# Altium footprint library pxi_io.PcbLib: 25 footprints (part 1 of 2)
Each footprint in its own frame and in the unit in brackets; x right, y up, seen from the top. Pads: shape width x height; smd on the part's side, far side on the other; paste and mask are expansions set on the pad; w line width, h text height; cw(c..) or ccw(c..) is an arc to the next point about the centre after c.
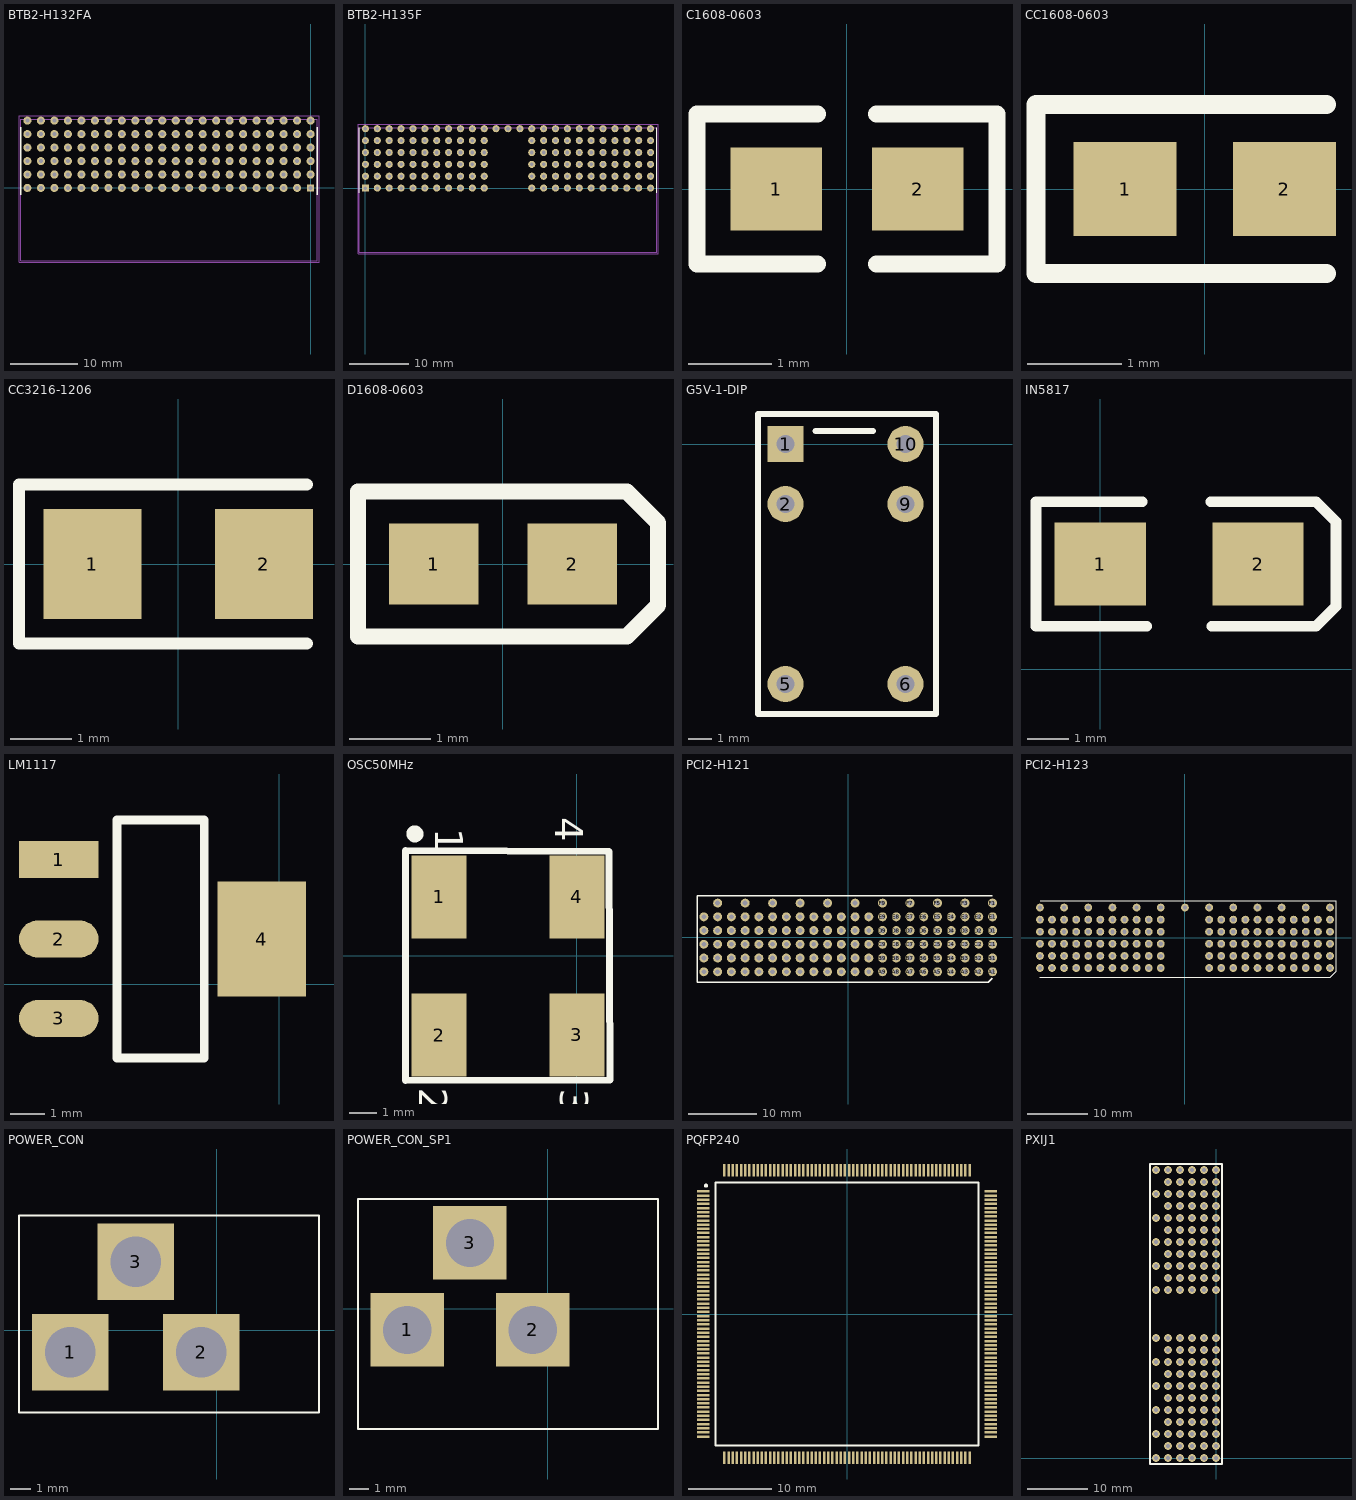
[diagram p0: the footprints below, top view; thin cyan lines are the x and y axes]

## BTB2-H132FA [mm] "Board-to-Board Connector, Right Angle, Pitch 2mm, 132-Position, Female"
height 7.7
pads (132):
  rect 1x1 / inner round 1.524 / far side round 1.524 hole 0.61: A1(0,0)
  round 1.2 hole 0.61: A2(-2,0) A3(-4,0) A4(-6,0) A5(-8,0) A6(-10,0) A7(-12,0) A8(-14,0) A9(-16,0) A10(-18,0) A11(-20,0) A12(-22,0) A13(-24,0) A14(-26,0) A15(-28,0) A16(-30,0) A17(-32,0) A18(-34,0) A19(-36,0) A20(-38,0) A21(-40,0) A22(-42,0) B1(0,2) B2(-2,2) B3(-4,2) B4(-6,2) B5(-8,2) B6(-10,2) B7(-12,2) B8(-14,2) B9(-16,2) B10(-18,2) B11(-20,2) B12(-22,2) B13(-24,2) B14(-26,2) B15(-28,2) B16(-30,2) B17(-32,2) B18(-34,2) B19(-36,2) B20(-38,2) B21(-40,2) B22(-42,2) C1(0,4) C2(-2,4) C3(-4,4) C4(-6,4) C5(-8,4) C6(-10,4) C7(-12,4) C8(-14,4) C9(-16,4) C10(-18,4) C11(-20,4) C12(-22,4) C13(-24,4) C14(-26,4) C15(-28,4) C16(-30,4) C17(-32,4) C18(-34,4) C19(-36,4) C20(-38,4) C21(-40,4) C22(-42,4) D1(0,6) D2(-2,6) D3(-4,6) D4(-6,6) D5(-8,6) D6(-10,6) D7(-12,6) D8(-14,6) D9(-16,6) D10(-18,6) D11(-20,6) D12(-22,6) D13(-24,6) D14(-26,6) D15(-28,6) D16(-30,6) D17(-32,6) D18(-34,6) D19(-36,6) D20(-38,6) D21(-40,6) D22(-42,6) E1(0,8) E2(-2,8) E3(-4,8) E4(-6,8) E5(-8,8) E6(-10,8) E7(-12,8) E8(-14,8) E9(-16,8) E10(-18,8) E11(-20,8) E12(-22,8) E13(-24,8) E14(-26,8) E15(-28,8) E16(-30,8) E17(-32,8) E18(-34,8) E19(-36,8) E20(-38,8) E21(-40,8) E22(-42,8) F1(0,10) F2(-2,10) F3(-4,10) F4(-6,10) F5(-8,10) F6(-10,10) F7(-12,10) F8(-14,10) F9(-16,10) F10(-18,10) F11(-20,10) F12(-22,10) F13(-24,10) F14(-26,10) F15(-28,10) F16(-30,10) F17(-32,10) F18(-34,10) F19(-36,10) F20(-38,10) F21(-40,10) F22(-42,10)
Top Overlay:
  lines w0.2: -43,-1 -43,9 ; 1,-1 1,9
Mechanical 13:
  lines w0.1: -43,-10.8 -43,10.2 1,10.2 1,-10.8 -43,-10.8
Mechanical 15:
  lines w0.1: -0.5,0 0.5,0 ; 0,-0.5 0,0.5 ; -43.25,-11.05 1.25,-11.05 1.25,10.75 -43.25,10.75 -43.25,-11.05
3D body: height 7.25, standoff 0, extent -43,-2 1,9.4
3D body: height 7.7, standoff -3.7, extent -43,-10.8 0.95,-2.032
3D body: height 7.39, standoff 0.7, extent -42.418,9.8 0.65,10.2
3D body: height 7.8, standoff 7.39, extent -42.418,0.972 0.65,10.2
3D body: height 7.8, standoff 7.39, extent -42.418,-6.38 0.65,0.972
3D body: height 0, standoff -3.3, extent -0.198,-0.199 0.2,0.2
3D body: height 0, standoff -3.3, extent -0.198,1.801 0.2,2.2
3D body: height 0, standoff -3.3, extent -0.198,3.801 0.2,4.2
3D body: height 0, standoff -3.3, extent -0.198,5.801 0.2,6.2
3D body: height 0, standoff -3.3, extent -0.198,7.801 0.2,8.2
3D body: height 0, standoff -3.3, extent -2.198,7.801 -1.8,8.2
3D body: height 0, standoff -3.3, extent -2.198,5.801 -1.8,6.2
3D body: height 0, standoff -3.3, extent -2.198,3.801 -1.8,4.2
3D body: height 0, standoff -3.3, extent -2.198,1.801 -1.8,2.2
3D body: height 0, standoff -3.3, extent -2.198,-0.199 -1.8,0.2
3D body: height 0, standoff -3.3, extent -4.198,7.801 -3.8,8.2
3D body: height 0, standoff -3.3, extent -4.198,5.801 -3.8,6.2
3D body: height 0, standoff -3.3, extent -4.198,3.801 -3.8,4.2
3D body: height 0, standoff -3.3, extent -4.198,1.801 -3.8,2.2
3D body: height 0, standoff -3.3, extent -4.198,-0.199 -3.8,0.2
3D body: height 0, standoff -3.3, extent -6.198,7.801 -5.8,8.2
3D body: height 0, standoff -3.3, extent -6.198,5.801 -5.8,6.2
3D body: height 0, standoff -3.3, extent -6.198,3.801 -5.8,4.2
3D body: height 0, standoff -3.3, extent -6.198,1.801 -5.8,2.2
3D body: height 0, standoff -3.3, extent -6.198,-0.199 -5.8,0.2
3D body: height 0, standoff -3.3, extent -8.198,7.801 -7.8,8.2
3D body: height 0, standoff -3.3, extent -8.198,5.801 -7.8,6.2
3D body: height 0, standoff -3.3, extent -8.198,3.801 -7.8,4.2
3D body: height 0, standoff -3.3, extent -8.198,1.801 -7.8,2.2
3D body: height 0, standoff -3.3, extent -8.198,-0.199 -7.8,0.2
3D body: height 0, standoff -3.3, extent -10.198,7.801 -9.8,8.2
3D body: height 0, standoff -3.3, extent -10.198,5.801 -9.8,6.2
3D body: height 0, standoff -3.3, extent -10.198,3.801 -9.8,4.2
3D body: height 0, standoff -3.3, extent -10.198,1.801 -9.8,2.2
3D body: height 0, standoff -3.3, extent -10.198,-0.199 -9.8,0.2
3D body: height 0, standoff -3.3, extent -12.198,7.801 -11.8,8.2
3D body: height 0, standoff -3.3, extent -12.198,5.801 -11.8,6.2
3D body: height 0, standoff -3.3, extent -12.198,3.801 -11.8,4.2
3D body: height 0, standoff -3.3, extent -12.198,1.801 -11.8,2.2
3D body: height 0, standoff -3.3, extent -12.198,-0.199 -11.8,0.2
3D body: height 0, standoff -3.3, extent -14.198,7.801 -13.8,8.2
3D body: height 0, standoff -3.3, extent -14.198,5.801 -13.8,6.2
3D body: height 0, standoff -3.3, extent -14.198,3.801 -13.8,4.2
3D body: height 0, standoff -3.3, extent -14.198,1.801 -13.8,2.2
3D body: height 0, standoff -3.3, extent -14.198,-0.199 -13.8,0.2
3D body: height 0, standoff -3.3, extent -16.198,7.801 -15.8,8.2
3D body: height 0, standoff -3.3, extent -16.198,5.801 -15.8,6.2
3D body: height 0, standoff -3.3, extent -16.198,3.801 -15.8,4.2
3D body: height 0, standoff -3.3, extent -16.198,1.801 -15.8,2.2
3D body: height 0, standoff -3.3, extent -16.198,-0.199 -15.8,0.2
3D body: height 0, standoff -3.3, extent -18.198,7.801 -17.8,8.2
3D body: height 0, standoff -3.3, extent -18.198,5.801 -17.8,6.2
3D body: height 0, standoff -3.3, extent -18.198,3.801 -17.8,4.2
3D body: height 0, standoff -3.3, extent -18.198,1.801 -17.8,2.2
3D body: height 0, standoff -3.3, extent -18.198,-0.199 -17.8,0.2
3D body: height 0, standoff -3.3, extent -20.198,7.801 -19.8,8.2
3D body: height 0, standoff -3.3, extent -20.198,5.801 -19.8,6.2
3D body: height 0, standoff -3.3, extent -20.198,3.801 -19.8,4.2
3D body: height 0, standoff -3.3, extent -20.198,1.801 -19.8,2.2
3D body: height 0, standoff -3.3, extent -20.198,-0.199 -19.8,0.2
3D body: height 0, standoff -3.3, extent -22.198,7.801 -21.8,8.2
3D body: height 0, standoff -3.3, extent -22.198,5.801 -21.8,6.2
3D body: height 0, standoff -3.3, extent -22.198,3.801 -21.8,4.2
3D body: height 0, standoff -3.3, extent -22.198,1.801 -21.8,2.2
3D body: height 0, standoff -3.3, extent -22.198,-0.199 -21.8,0.2
3D body: height 0, standoff -3.3, extent -24.198,7.801 -23.8,8.2
3D body: height 0, standoff -3.3, extent -24.198,5.801 -23.8,6.2
3D body: height 0, standoff -3.3, extent -24.198,3.801 -23.8,4.2
3D body: height 0, standoff -3.3, extent -24.198,1.801 -23.8,2.2
3D body: height 0, standoff -3.3, extent -24.198,-0.199 -23.8,0.2
3D body: height 0, standoff -3.3, extent -26.198,7.801 -25.8,8.2
3D body: height 0, standoff -3.3, extent -26.198,5.801 -25.8,6.2
3D body: height 0, standoff -3.3, extent -26.198,3.801 -25.8,4.2
3D body: height 0, standoff -3.3, extent -26.198,1.801 -25.8,2.2
3D body: height 0, standoff -3.3, extent -26.198,-0.199 -25.8,0.2
3D body: height 0, standoff -3.3, extent -28.198,7.801 -27.8,8.2
3D body: height 0, standoff -3.3, extent -28.198,5.801 -27.8,6.2
3D body: height 0, standoff -3.3, extent -28.198,3.801 -27.8,4.2
3D body: height 0, standoff -3.3, extent -28.198,1.801 -27.8,2.2
3D body: height 0, standoff -3.3, extent -28.198,-0.199 -27.8,0.2
3D body: height 0, standoff -3.3, extent -30.198,7.801 -29.8,8.2
3D body: height 0, standoff -3.3, extent -30.198,5.801 -29.8,6.2
3D body: height 0, standoff -3.3, extent -30.198,3.801 -29.8,4.2
3D body: height 0, standoff -3.3, extent -30.198,1.801 -29.8,2.2
3D body: height 0, standoff -3.3, extent -30.198,-0.199 -29.8,0.2
3D body: height 0, standoff -3.3, extent -32.198,7.801 -31.8,8.2
3D body: height 0, standoff -3.3, extent -32.198,5.801 -31.8,6.2
3D body: height 0, standoff -3.3, extent -32.198,3.801 -31.8,4.2
3D body: height 0, standoff -3.3, extent -32.198,1.801 -31.8,2.2
3D body: height 0, standoff -3.3, extent -32.198,-0.199 -31.8,0.2
3D body: height 0, standoff -3.3, extent -34.198,7.801 -33.8,8.2
3D body: height 0, standoff -3.3, extent -34.198,5.801 -33.8,6.2
3D body: height 0, standoff -3.3, extent -34.198,3.801 -33.8,4.2
3D body: height 0, standoff -3.3, extent -34.198,1.801 -33.8,2.2
3D body: height 0, standoff -3.3, extent -34.198,-0.199 -33.8,0.2
3D body: height 0, standoff -3.3, extent -36.198,7.801 -35.8,8.2
3D body: height 0, standoff -3.3, extent -36.198,5.801 -35.8,6.2
3D body: height 0, standoff -3.3, extent -36.198,3.801 -35.8,4.2
3D body: height 0, standoff -3.3, extent -36.198,1.801 -35.8,2.2
3D body: height 0, standoff -3.3, extent -36.198,-0.199 -35.8,0.2
3D body: height 0, standoff -3.3, extent -38.198,-0.199 -37.8,0.2
3D body: height 0, standoff -3.3, extent -38.198,1.801 -37.8,2.2
3D body: height 0, standoff -3.3, extent -38.198,3.801 -37.8,4.2
3D body: height 0, standoff -3.3, extent -38.198,5.801 -37.8,6.2
3D body: height 0, standoff -3.3, extent -38.198,7.801 -37.8,8.2
3D body: height 0, standoff -3.3, extent -40.198,-0.199 -39.8,0.2
3D body: height 0, standoff -3.3, extent -40.198,1.801 -39.8,2.2
3D body: height 0, standoff -3.3, extent -40.198,3.801 -39.8,4.2
3D body: height 0, standoff -3.3, extent -40.198,5.801 -39.8,6.2
3D body: height 0, standoff -3.3, extent -40.198,7.801 -39.8,8.2
3D body: height 0, standoff -3.3, extent -42.198,-0.2 -41.8,0.2
3D body: height 0, standoff -3.3, extent -42.198,1.8 -41.8,2.2
3D body: height 0, standoff -3.3, extent -42.198,3.8 -41.8,4.2
3D body: height 0, standoff -3.3, extent -42.198,5.8 -41.8,6.2
3D body: height 0, standoff -3.3, extent -42.198,7.8 -41.8,8.2
3D body: height 0.7, standoff -3.3, extent -40.198,9.8 -39.8,10.2
3D body: height 0.7, standoff -3.3, extent -0.198,9.8 0.2,10.2
3D body: height 0.7, standoff -3.3, extent -4.198,9.8 -3.8,10.2
3D body: height 0.7, standoff -3.3, extent -8.198,9.8 -7.8,10.2
3D body: height 0.7, standoff -3.3, extent -12.198,9.8 -11.8,10.2
3D body: height 0.7, standoff -3.3, extent -16.198,9.8 -15.8,10.2
3D body: height 0.7, standoff -3.3, extent -20.198,9.8 -19.8,10.2
3D body: height 0.7, standoff -3.3, extent -24.198,9.8 -23.8,10.2
3D body: height 0.7, standoff -3.3, extent -28.198,9.8 -27.8,10.2
3D body: height 0.7, standoff -3.3, extent -32.198,9.8 -31.8,10.2
3D body: height 0.7, standoff -3.3, extent -36.198,9.8 -35.8,10.2

## BTB2-H135F [mm] "Board-to-Board Connector, Right Angle, Pitch 2mm, 135-Position, Female"
pads (135):
  rect 1.2x1.2 hole 0.61: A1(0,0)
  round 1.2 hole 0.61: A2(2,0) A3(4,0) A4(6,0) A5(8,0) A6(10,0) A7(12,0) A8(14,0) A9(16,0) A10(18,0) A11(20,0) A15(28,0) A16(30,0) A17(32,0) A18(34,0) A19(36,0) A20(38,0) A21(40,0) A22(42,0) A23(44,0) A24(46,0) A25(48,0) B1(0,2) B2(2,2) B3(4,2) B4(6,2) B5(8,2) B6(10,2) B7(12,2) B8(14,2) B9(16,2) B10(18,2) B11(20,2) B15(28,2) B16(30,2) B17(32,2) B18(34,2) B19(36,2) B20(38,2) B21(40,2) B22(42,2) B23(44,2) B24(46,2) B25(48,2) C1(0,4) C2(2,4) C3(4,4) C4(6,4) C5(8,4) C6(10,4) C7(12,4) C8(14,4) C9(16,4) C10(18,4) C11(20,4) C15(28,4) C16(30,4) C17(32,4) C18(34,4) C19(36,4) C20(38,4) C21(40,4) C22(42,4) C23(44,4) C24(46,4) C25(48,4) D1(0,6) D2(2,6) D3(4,6) D4(6,6) D5(8,6) D6(10,6) D7(12,6) D8(14,6) D9(16,6) D10(18,6) D11(20,6) D15(28,6) D16(30,6) D17(32,6) D18(34,6) D19(36,6) D20(38,6) D21(40,6) D22(42,6) D23(44,6) D24(46,6) D25(48,6) E1(0,8) E2(2,8) E3(4,8) E4(6,8) E5(8,8) E6(10,8) E7(12,8) E8(14,8) E9(16,8) E10(18,8) E11(20,8) E15(28,8) E16(30,8) E17(32,8) E18(34,8) E19(36,8) E20(38,8) E21(40,8) E22(42,8) E23(44,8) E24(46,8) E25(48,8) F1(0,10) F2(2,10) F3(4,10) F4(6,10) F5(8,10) F6(10,10) F7(12,10) F8(14,10) F9(16,10) F10(18,10) F11(20,10) F12(22,10) F13(24,10) F14(26,10) F15(28,10) F16(30,10) F17(32,10) F18(34,10) F19(36,10) F20(38,10) F21(40,10) F22(42,10) F23(44,10) F24(46,10) F25(48,10)
Top Overlay:
  lines w0.2: -1,-0.8 -1,10.2 ; 49,-0.8 49,10.2
Mechanical 13:
  lines w0.1: -1,-10.8 49,-10.8 49,10.2 -1,10.2 -1,-10.8
Mechanical 15:
  lines w0.1: -0.5,0 0.5,0 ; 0,-0.5 0,0.5 ; -1.25,-11.05 49.25,-11.05 49.25,10.75 -1.25,10.75 -1.25,-11.05
3D body: height 8.08, standoff 6.75, extent 22.175,-13.8 25.825,-8.725
3D body: height -2.85, standoff -4.18, extent 22.5,-13.8 25.5,-8.725
3D body: height 7.65, standoff 6.75, extent 22.175,-8.725 25.825,-2.65
3D body: height -2.85, standoff -3.75, extent 22.175,-8.725 25.825,-2.65
3D body: height 7.65, standoff 0.5, extent 27,-10.8 48.95,-0.9
3D body: height 7.65, standoff 0.5, extent -0.95,-10.8 21,-0.9
3D body: height 2.87, standoff 0, extent 27,8.9 48.95,9.4
3D body: height 2.87, standoff 0, extent -0.95,8.9 21,9.4
3D body: height 7.25, standoff 0.5, extent 27,-0.9 48.95,8.9
3D body: height 7.25, standoff 0.5, extent -0.95,-0.9 21,8.9
3D body: height 0.5, standoff 0, extent 27,-2 48.95,-0.9
3D body: height 0.5, standoff 0, extent -0.95,-2 21,-0.9
3D body: height 3.26, standoff -0.94, extent -0.95,-10.8 21,-2
3D body: height 3.26, standoff -0.94, extent 27,-10.8 48.95,-2
3D body: height 2.91, standoff -1.29, extent -0.268,9.731 0.27,10.27
3D body: height 2.91, standoff -1.29, extent 3.732,9.731 4.27,10.27
3D body: height 2.91, standoff -1.29, extent 7.732,9.731 8.27,10.27
3D body: height 2.91, standoff -1.29, extent 11.732,9.731 12.27,10.27
3D body: height 2.91, standoff -1.29, extent 15.732,9.731 16.27,10.27
3D body: height 2.91, standoff -1.29, extent 19.732,9.731 20.27,10.27
3D body: height 2.91, standoff -1.29, extent 23.732,9.731 24.27,10.27
3D body: height 2.91, standoff -1.29, extent 27.732,9.731 28.27,10.27
3D body: height 2.91, standoff -1.29, extent 31.732,9.731 32.27,10.27
3D body: height 2.91, standoff -1.29, extent 35.732,9.731 36.27,10.27
3D body: height 2.91, standoff -1.29, extent 39.732,9.731 40.27,10.27
3D body: height 2.91, standoff -1.29, extent 43.732,9.731 44.27,10.27
3D body: height 2.91, standoff -1.29, extent 47.732,9.731 48.27,10.27
3D body: height 2.86, standoff -0.94, extent 47.702,7.701 48.3,8.299
3D body: height 2.86, standoff -0.94, extent -0.298,7.701 0.3,8.3
3D body: height 2.86, standoff -0.94, extent 1.702,7.701 2.3,8.3
3D body: height 2.86, standoff -0.94, extent 3.702,7.701 4.3,8.3
3D body: height 2.86, standoff -0.94, extent 5.702,7.701 6.3,8.3
3D body: height 2.86, standoff -0.94, extent 7.702,7.701 8.3,8.3
3D body: height 2.86, standoff -0.94, extent 9.702,7.701 10.3,8.3
3D body: height 2.86, standoff -0.94, extent 11.702,7.701 12.3,8.3
3D body: height 2.86, standoff -0.94, extent 13.702,7.701 14.3,8.3
3D body: height 2.86, standoff -0.94, extent 15.702,7.701 16.3,8.3
3D body: height 2.86, standoff -0.94, extent 17.702,7.701 18.3,8.3
3D body: height 2.86, standoff -0.94, extent 19.702,7.701 20.3,8.3
3D body: height 2.86, standoff -0.94, extent -0.298,5.701 0.3,6.3
3D body: height 2.86, standoff -0.94, extent 1.702,5.701 2.3,6.3
3D body: height 2.86, standoff -0.94, extent 3.702,5.701 4.3,6.3
3D body: height 2.86, standoff -0.94, extent 5.702,5.701 6.3,6.3
3D body: height 2.86, standoff -0.94, extent 7.702,5.701 8.3,6.3
3D body: height 2.86, standoff -0.94, extent 9.702,5.701 10.3,6.3
3D body: height 2.86, standoff -0.94, extent 11.702,5.701 12.3,6.3
3D body: height 2.86, standoff -0.94, extent 13.702,5.701 14.3,6.3
3D body: height 2.86, standoff -0.94, extent 15.702,5.701 16.3,6.3
3D body: height 2.86, standoff -0.94, extent 17.702,5.701 18.3,6.3
3D body: height 2.86, standoff -0.94, extent 19.702,5.701 20.3,6.3
3D body: height 2.86, standoff -0.94, extent 19.702,3.701 20.3,4.299
3D body: height 2.86, standoff -0.94, extent 17.702,3.701 18.3,4.299
3D body: height 2.86, standoff -0.94, extent 15.702,3.701 16.3,4.299
3D body: height 2.86, standoff -0.94, extent 13.702,3.701 14.3,4.299
3D body: height 2.86, standoff -0.94, extent 11.702,3.701 12.3,4.299
3D body: height 2.86, standoff -0.94, extent 9.702,3.701 10.3,4.299
3D body: height 2.86, standoff -0.94, extent 7.702,3.701 8.3,4.299
3D body: height 2.86, standoff -0.94, extent 5.702,3.701 6.3,4.299
3D body: height 2.86, standoff -0.94, extent 3.702,3.701 4.3,4.299
3D body: height 2.86, standoff -0.94, extent 1.702,3.701 2.3,4.299
3D body: height 2.86, standoff -0.94, extent -0.298,3.701 0.3,4.299
3D body: height 2.86, standoff -0.94, extent 19.702,1.701 20.3,2.299
3D body: height 2.86, standoff -0.94, extent 17.702,1.701 18.3,2.299
3D body: height 2.86, standoff -0.94, extent 15.702,1.701 16.3,2.299
3D body: height 2.86, standoff -0.94, extent 13.702,1.701 14.3,2.299
3D body: height 2.86, standoff -0.94, extent 11.702,1.701 12.3,2.299
3D body: height 2.86, standoff -0.94, extent 9.702,1.701 10.3,2.299
3D body: height 2.86, standoff -0.94, extent 7.702,1.701 8.3,2.299
3D body: height 2.86, standoff -0.94, extent 5.702,1.701 6.3,2.299
3D body: height 2.86, standoff -0.94, extent 3.702,1.701 4.3,2.299
3D body: height 2.86, standoff -0.94, extent 1.702,1.701 2.3,2.299
3D body: height 2.86, standoff -0.94, extent -0.298,1.701 0.3,2.299
3D body: height 2.86, standoff -0.94, extent 19.702,-0.299 20.3,0.299
3D body: height 2.86, standoff -0.94, extent 17.702,-0.299 18.3,0.299
3D body: height 2.86, standoff -0.94, extent 15.702,-0.299 16.3,0.299
3D body: height 2.86, standoff -0.94, extent 13.702,-0.299 14.3,0.299
3D body: height 2.86, standoff -0.94, extent 11.702,-0.299 12.3,0.299
3D body: height 2.86, standoff -0.94, extent 9.702,-0.299 10.3,0.299
3D body: height 2.86, standoff -0.94, extent 7.702,-0.299 8.3,0.299
3D body: height 2.86, standoff -0.94, extent 5.702,-0.299 6.3,0.299
3D body: height 2.86, standoff -0.94, extent 3.702,-0.299 4.3,0.299
3D body: height 2.86, standoff -0.94, extent 1.702,-0.299 2.3,0.299
3D body: height 2.86, standoff -0.94, extent -0.298,-0.299 0.3,0.299
3D body: height 2.86, standoff -0.94, extent 47.702,-0.299 48.3,0.3
3D body: height 2.86, standoff -0.94, extent 45.702,-0.299 46.3,0.3
3D body: height 2.86, standoff -0.94, extent 43.702,-0.299 44.3,0.3
3D body: height 2.86, standoff -0.94, extent 41.702,-0.299 42.3,0.3
3D body: height 2.86, standoff -0.94, extent 39.702,-0.299 40.3,0.3
3D body: height 2.86, standoff -0.94, extent 37.702,-0.299 38.3,0.3
3D body: height 2.86, standoff -0.94, extent 35.702,-0.299 36.3,0.3
3D body: height 2.86, standoff -0.94, extent 33.702,-0.299 34.3,0.3
3D body: height 2.86, standoff -0.94, extent 31.702,-0.299 32.3,0.3
3D body: height 2.86, standoff -0.94, extent 29.702,-0.299 30.3,0.3
3D body: height 2.86, standoff -0.94, extent 27.702,-0.299 28.3,0.3
3D body: height 2.86, standoff -0.94, extent 47.702,1.701 48.3,2.299
3D body: height 2.86, standoff -0.94, extent 45.702,1.701 46.3,2.299
3D body: height 2.86, standoff -0.94, extent 43.702,1.701 44.3,2.299
3D body: height 2.86, standoff -0.94, extent 41.702,1.701 42.3,2.299
3D body: height 2.86, standoff -0.94, extent 39.702,1.701 40.3,2.299
3D body: height 2.86, standoff -0.94, extent 37.702,1.701 38.3,2.299
3D body: height 2.86, standoff -0.94, extent 35.702,1.701 36.3,2.299
3D body: height 2.86, standoff -0.94, extent 33.702,1.701 34.3,2.299
3D body: height 2.86, standoff -0.94, extent 31.702,1.701 32.3,2.299
3D body: height 2.86, standoff -0.94, extent 29.702,1.701 30.3,2.299
3D body: height 2.86, standoff -0.94, extent 27.702,1.701 28.3,2.299
3D body: height 2.86, standoff -0.94, extent 47.702,3.701 48.3,4.299
3D body: height 2.86, standoff -0.94, extent 45.702,3.701 46.3,4.299
3D body: height 2.86, standoff -0.94, extent 43.702,3.701 44.3,4.299
3D body: height 2.86, standoff -0.94, extent 41.702,3.701 42.3,4.299
3D body: height 2.86, standoff -0.94, extent 39.702,3.701 40.3,4.299
3D body: height 2.86, standoff -0.94, extent 37.702,3.701 38.3,4.299
3D body: height 2.86, standoff -0.94, extent 35.702,3.701 36.3,4.299
3D body: height 2.86, standoff -0.94, extent 33.702,3.701 34.3,4.299
3D body: height 2.86, standoff -0.94, extent 31.702,3.701 32.3,4.299
3D body: height 2.86, standoff -0.94, extent 29.702,3.701 30.3,4.299
3D body: height 2.86, standoff -0.94, extent 27.702,3.701 28.3,4.299
3D body: height 2.86, standoff -0.94, extent 47.702,5.701 48.3,6.299
3D body: height 2.86, standoff -0.94, extent 45.702,5.701 46.3,6.299
3D body: height 2.86, standoff -0.94, extent 43.702,5.701 44.3,6.299
3D body: height 2.86, standoff -0.94, extent 41.702,5.701 42.3,6.299
3D body: height 2.86, standoff -0.94, extent 39.702,5.701 40.3,6.299
3D body: height 2.86, standoff -0.94, extent 37.702,5.701 38.3,6.299
3D body: height 2.86, standoff -0.94, extent 35.702,5.701 36.3,6.299
3D body: height 2.86, standoff -0.94, extent 33.702,5.701 34.3,6.299
3D body: height 2.86, standoff -0.94, extent 31.702,5.701 32.3,6.299
3D body: height 2.86, standoff -0.94, extent 29.702,5.701 30.3,6.299
3D body: height 2.86, standoff -0.94, extent 27.702,5.701 28.3,6.299
3D body: height 2.86, standoff -0.94, extent 45.702,7.701 46.3,8.299
3D body: height 2.86, standoff -0.94, extent 43.702,7.701 44.3,8.299
3D body: height 2.86, standoff -0.94, extent 41.702,7.701 42.3,8.299
3D body: height 2.86, standoff -0.94, extent 39.702,7.701 40.3,8.299
3D body: height 2.86, standoff -0.94, extent 37.702,7.701 38.3,8.299
3D body: height 2.86, standoff -0.94, extent 35.702,7.701 36.3,8.299
3D body: height 2.86, standoff -0.94, extent 33.702,7.701 34.3,8.299
3D body: height 2.86, standoff -0.94, extent 31.702,7.701 32.3,8.299
3D body: height 2.86, standoff -0.94, extent 29.702,7.701 30.3,8.299
3D body: height 2.86, standoff -0.94, extent 27.702,7.701 28.3,8.299
3D body: height 7.65, standoff 0.85, extent -0.85,9.8 48.85,10.2
3D body: height 7.65, standoff 7.25, extent -0.85,-2 48.85,10.2
3D body: height 7.65, standoff -2.96, extent 21,-2.65 27,-2

## C1608-0603 [mm]
pads (2):
  rect 1.1x1 smd: 1(-0.85,0) 2(0.85,0)
Top Overlay:
  lines w0.2: -0.35,-0.9 -1.8,-0.9 -1.8,0.9 -0.35,0.9 ; 0.35,-0.9 1.8,-0.9 1.8,0.9 0.35,0.9

## CC1608-0603 [mm]
pads (2):
  rect 1.1x1 smd: 1(-0.85,0) 2(0.85,0)
Top Overlay:
  lines w0.2: 1.3,-0.9 -1.8,-0.9 -1.8,0.9 1.3,0.9

## CC3216-1206 [mm]
pads (2):
  rect 1.6x1.8 smd: 1(-1.4,0) 2(1.4,0)
Top Overlay:
  lines w0.2: 2.1,-1.3 -2.6,-1.3 -2.6,1.3 2.1,1.3

## D1608-0603 [mm]
pads (2):
  rect 1.1x1 smd: 1(-0.85,0) 2(0.85,0)
Top Overlay:
  lines w0.2: 1.27,-0.889 1.524,-0.889 1.905,-0.508 1.905,0.508 1.524,0.889 1.27,0.889 ; 1.3,-0.889 -1.778,-0.889 -1.778,0.889 1.3,0.889

## G5V-1-DIP [mil]
pads (6):
  rect 60x60 hole 30: 1(200,0)
  round 60 hole 30: 2(200,-100) 5(200,-400) 6(400,-400) 9(400,-100) 10(400,0)
Top Overlay:
  lines w10: 250,22 346,22 ; 154,-450 154,50 451,50 451,-450 154,-450

## IN5817 [mm]
pads (2):
  rect 2.2x2 smd: 1(0,2.54) 2(3.81,2.54)
Top Overlay:
  lines w0.254: 1.016,4.039 -1.549,4.039 -1.549,1.041 1.118,1.041 ; 2.667,4.039 5.207,4.039 5.69,3.556 5.69,1.524 5.207,1.041 2.692,1.041

## LM1117 [mil]
pads (4):
  rect 90x42 smd: 1(-250,141)
  oval 90x42 smd: 2(-250,51) 3(-250,-39)
  rect 100x130 smd: 4(-20,51)
Top Overlay:
  lines w10: -99,186 -184,186 -184,-84 -85,-84 -85,186 -97.5,186

## OSC50MHz [mm] "for 50MHz"
height 3.5
pads (4):
  rect 2x3 smd: 1(-5,2.134) 2(-5,-2.87) 3(0,-2.866) 4(0,2.134)
Top Overlay:
  circle w0.5: c-5.873,4.42 r0.057
  lines w0.254: -6.223,-4.521 -6.223,3.81 1.168,3.785 1.194,-4.496 -6.223,-4.521
  text "4" at -0.787,5.029 h1.02
  text "3" at -0.61,-4.826 h1.02
  text "2" at -5.715,-4.775 h1.02
  text "1" at -5.131,4.623 h1.02

## PCI2-H121 [mm]
pads (121):
  round 1.3 hole 0.7: A1(21,-5) A2(19,-5) A3(17,-5) A4(15,-5) A5(13,-5) A6(11,-5) A7(9,-5) A8(7,-5) A9(5,-5) A10(3,-5) A11(1,-5) A12(-1,-5) A13(-3,-5) A14(-5,-5) A15(-7,-5) A16(-9,-5) A17(-11,-5) A18(-13,-5) A19(-15,-5) A20(-17,-5) A21(-19,-5) A22(-21,-5) B1(21,-3) B2(19,-3) B3(17,-3) B4(15,-3) B5(13,-3) B6(11,-3) B7(9,-3) B8(7,-3) B9(5,-3) B10(3,-3) B11(1,-3) B12(-1,-3) B13(-3,-3) B14(-5,-3) B15(-7,-3) B16(-9,-3) B17(-11,-3) B18(-13,-3) B19(-15,-3) B20(-17,-3) B21(-19,-3) B22(-21,-3) C1(21,-1) C2(19,-1) C3(17,-1) C4(15,-1) C5(13,-1) C6(11,-1) C7(9,-1) C8(7,-1) C9(5,-1) C10(3,-1) C11(1,-1) C12(-1,-1) C13(-3,-1) C14(-5,-1) C15(-7,-1) C16(-9,-1) C17(-11,-1) C18(-13,-1) C19(-15,-1) C20(-17,-1) C21(-19,-1) C22(-21,-1) D1(21,1) D2(19,1) D3(17,1) D4(15,1) D5(13,1) D6(11,1) D7(9,1) D8(7,1) D9(5,1) D10(3,1) D11(1,1) D12(-1,1) D13(-3,1) D14(-5,1) D15(-7,1) D16(-9,1) D17(-11,1) D18(-13,1) D19(-15,1) D20(-17,1) D21(-19,1) D22(-21,1) E1(21,3) E2(19,3) E3(17,3) E4(15,3) E5(13,3) E6(11,3) E7(9,3) E8(7,3) E9(5,3) E10(3,3) E11(1,3) E12(-1,3) E13(-3,3) E14(-5,3) E15(-7,3) E16(-9,3) E17(-11,3) E18(-13,3) E19(-15,3) E20(-17,3) E21(-19,3) E22(-21,3) F1(21,5) F3(17,5) F5(13,5) F7(9,5) F9(5,5) F11(1,5) F13(-3,5) F15(-7,5) F17(-11,5) F19(-15,5) F21(-19,5)
Top Overlay:
  lines w0.2: 20.371,-6.502 -22,-6.5 -22,6.05 20.93,6.045
  lines w0.203: 20.371,-6.502 20.93,-5.944

## PCI2-H123 [mm]
pads (123):
  round 1.3 hole 0.7: A1(24,-5) A2(22,-5) A3(20,-5) A4(18,-5) A5(16,-5) A6(14,-5) A7(12,-5) A8(10,-5) A9(8,-5) A10(6,-5) A11(4,-5) A15(-4,-5) A16(-6,-5) A17(-8,-5) A18(-10,-5) A19(-12,-5) A20(-14,-5) A21(-16,-5) A22(-18,-5) A23(-20,-5) A24(-22,-5) A25(-24,-5) B1(24,-3) B2(22,-3) B3(20,-3) B4(18,-3) B5(16,-3) B6(14,-3) B7(12,-3) B8(10,-3) B9(8,-3) B10(6,-3) B11(4,-3) B15(-4,-3) B16(-6,-3) B17(-8,-3) B18(-10,-3) B19(-12,-3) B20(-14,-3) B21(-16,-3) B22(-18,-3) B23(-20,-3) B24(-22,-3) B25(-24,-3) C1(24,-1) C2(22,-1) C3(20,-1) C4(18,-1) C5(16,-1) C6(14,-1) C7(12,-1) C8(10,-1) C9(8,-1) C10(6,-1) C11(4,-1) C15(-4,-1) C16(-6,-1) C17(-8,-1) C18(-10,-1) C19(-12,-1) C20(-14,-1) C21(-16,-1) C22(-18,-1) C23(-20,-1) C24(-22,-1) C25(-24,-1) D1(24,1) D2(22,1) D3(20,1) D4(18,1) D5(16,1) D6(14,1) D7(12,1) D8(10,1) D9(8,1) D10(6,1) D11(4,1) D15(-4,1) D16(-6,1) D17(-8,1) D18(-10,1) D19(-12,1) D20(-14,1) D21(-16,1) D22(-18,1) D23(-20,1) D24(-22,1) D25(-24,1) E1(24,3) E2(22,3) E3(20,3) E4(18,3) E5(16,3) E6(14,3) E7(12,3) E8(10,3) E9(8,3) E10(6,3) E11(4,3) E15(-4,3) E16(-6,3) E17(-8,3) E18(-10,3) E19(-12,3) E20(-14,3) E21(-16,3) E22(-18,3) E23(-20,3) E24(-22,3) E25(-24,3) F1(24,5) F3(20,5) F5(16,5) F7(12,5) F9(8,5) F11(4,5) F13(0,5) F15(-4,5) F17(-8,5) F19(-12,5) F21(-16,5) F23(-20,5) F25(-24,5)
Top Overlay:
  lines w0.2: -24.028,-6.502 24.028,-6.5 25,-5.528 25,6.1 -23.978,6.096
  lines w0.203: 24.028,-6.5 25,-5.528 25,-5.283

## POWER_CON [mm]
pads (3):
  rect 3.8x3.8 hole 2.5: 1(-7.264,-1.092) 2(-0.764,-1.092) 3(-4.014,3.408)
Top Overlay:
  lines w0.102: -9.804,-4.064 5.08,-4.064 5.08,5.69 -9.804,5.69 -9.804,-4.064

## POWER_CON_SP1 [mm]
pads (3):
  rect 3.8x3.8 hole 2.5: 1(-7.264,-1.092) 2(-0.764,-1.092) 3(-4.014,3.408)
Top Overlay:
  lines w0.102: -9.804,-6.223 5.715,-6.223 5.715,5.69 -9.804,5.69 -9.804,-6.223

## PQFP240 [mm] "byTX chaned for cyclone FPGA"
pads (240):
  rect 1.5x0.3 smd: 1(-17.3,14.75) 2(-17.3,14.25) 3(-17.3,13.75) 4(-17.3,13.25) 5(-17.3,12.75) 6(-17.3,12.25) 7(-17.3,11.75) 8(-17.3,11.25) 9(-17.3,10.75) 10(-17.3,10.25) 11(-17.3,9.75) 12(-17.3,9.25) 13(-17.3,8.75) 14(-17.3,8.25) 15(-17.3,7.75) 16(-17.3,7.25) 17(-17.3,6.75) 18(-17.3,6.25) 19(-17.3,5.75) 20(-17.3,5.25) 21(-17.3,4.75) 22(-17.3,4.25) 23(-17.3,3.75) 24(-17.3,3.25) 25(-17.3,2.75) 26(-17.3,2.25) 27(-17.3,1.75) 28(-17.3,1.25) 29(-17.3,0.75) 30(-17.3,0.25) 31(-17.3,-0.25) 32(-17.3,-0.75) 33(-17.3,-1.25) 34(-17.3,-1.75) 35(-17.3,-2.25) 36(-17.3,-2.75) 37(-17.3,-3.25) 38(-17.3,-3.75) 39(-17.3,-4.25) 40(-17.3,-4.75) 41(-17.3,-5.25) 42(-17.3,-5.75) 43(-17.3,-6.25) 44(-17.3,-6.75) 45(-17.3,-7.25) 46(-17.3,-7.75) 47(-17.3,-8.25) 48(-17.3,-8.75) 49(-17.3,-9.25) 50(-17.3,-9.75) 51(-17.3,-10.25) 52(-17.3,-10.75) 53(-17.3,-11.25) 54(-17.3,-11.75) 55(-17.3,-12.25) 56(-17.3,-12.75) 57(-17.3,-13.25) 58(-17.3,-13.75) 59(-17.3,-14.25) 60(-17.3,-14.75) 121(17.3,-14.75) 122(17.3,-14.25) 123(17.3,-13.75) 124(17.3,-13.25) 125(17.3,-12.75) 126(17.3,-12.25) 127(17.3,-11.75) 128(17.3,-11.25) 129(17.3,-10.75) 130(17.3,-10.25) 131(17.3,-9.75) 132(17.3,-9.25) 133(17.3,-8.75) 134(17.3,-8.25) 135(17.3,-7.75) 136(17.3,-7.25) 137(17.3,-6.75) 138(17.3,-6.25) 139(17.3,-5.75) 140(17.3,-5.25) 141(17.3,-4.75) 142(17.3,-4.25) 143(17.3,-3.75) 144(17.3,-3.25) 145(17.3,-2.75) 146(17.3,-2.25) 147(17.3,-1.75) 148(17.3,-1.25) 149(17.3,-0.75) 150(17.3,-0.25) 151(17.3,0.25) 152(17.3,0.75) 153(17.3,1.25) 154(17.3,1.75) 155(17.3,2.25) 156(17.3,2.75) 157(17.3,3.25) 158(17.3,3.75) 159(17.3,4.25) 160(17.3,4.75) 161(17.3,5.25) 162(17.3,5.75) 163(17.3,6.25) 164(17.3,6.75) 165(17.3,7.25) 166(17.3,7.75) 167(17.3,8.25) 168(17.3,8.75) 169(17.3,9.25) 170(17.3,9.75) 171(17.3,10.25) 172(17.3,10.75) 173(17.3,11.25) 174(17.3,11.75) 175(17.3,12.25) 176(17.3,12.75) 177(17.3,13.25) 178(17.3,13.75) 179(17.3,14.25) 180(17.3,14.75)
  rect 0.3x1.5 smd: 61(-14.75,-17.3) 62(-14.25,-17.3) 63(-13.75,-17.3) 64(-13.25,-17.3) 65(-12.75,-17.3) 66(-12.25,-17.3) 67(-11.75,-17.3) 68(-11.25,-17.3) 69(-10.75,-17.3) 70(-10.25,-17.3) 71(-9.75,-17.3) 72(-9.25,-17.3) 73(-8.75,-17.3) 74(-8.25,-17.3) 75(-7.75,-17.3) 76(-7.25,-17.3) 77(-6.75,-17.3) 78(-6.25,-17.3) 79(-5.75,-17.3) 80(-5.25,-17.3) 81(-4.75,-17.3) 82(-4.25,-17.3) 83(-3.75,-17.3) 84(-3.25,-17.3) 85(-2.75,-17.3) 86(-2.25,-17.3) 87(-1.75,-17.3) 88(-1.25,-17.3) 89(-0.75,-17.3) 90(-0.25,-17.3) 91(0.25,-17.3) 92(0.75,-17.3) 93(1.25,-17.3) 94(1.75,-17.3) 95(2.25,-17.3) 96(2.75,-17.3) 97(3.25,-17.3) 98(3.75,-17.3) 99(4.25,-17.3) 100(4.75,-17.3) 101(5.25,-17.3) 102(5.75,-17.3) 103(6.25,-17.3) 104(6.75,-17.3) 105(7.25,-17.3) 106(7.75,-17.3) 107(8.25,-17.3) 108(8.75,-17.3) 109(9.25,-17.3) 110(9.75,-17.3) 111(10.25,-17.3) 112(10.75,-17.3) 113(11.25,-17.3) 114(11.75,-17.3) 115(12.25,-17.3) 116(12.75,-17.3) 117(13.25,-17.3) 118(13.75,-17.3) 119(14.25,-17.3) 120(14.75,-17.3) 181(14.75,17.3) 182(14.25,17.3) 183(13.75,17.3) 184(13.25,17.3) 185(12.75,17.3) 186(12.25,17.3) 187(11.75,17.3) 188(11.25,17.3) 189(10.75,17.3) 190(10.25,17.3) 191(9.75,17.3) 192(9.25,17.3) 193(8.75,17.3) 194(8.25,17.3) 195(7.75,17.3) 196(7.25,17.3) 197(6.75,17.3) 198(6.25,17.3) 199(5.75,17.3) 200(5.25,17.3) 201(4.75,17.3) 202(4.25,17.3) 203(3.75,17.3) 204(3.25,17.3) 205(2.75,17.3) 206(2.25,17.3) 207(1.75,17.3) 208(1.25,17.3) 209(0.75,17.3) 210(0.25,17.3) 211(-0.25,17.3) 212(-0.75,17.3) 213(-1.25,17.3) 214(-1.75,17.3) 215(-2.25,17.3) 216(-2.75,17.3) 217(-3.25,17.3) 218(-3.75,17.3) 219(-4.25,17.3) 220(-4.75,17.3) 221(-5.25,17.3) 222(-5.75,17.3) 223(-6.25,17.3) 224(-6.75,17.3) 225(-7.25,17.3) 226(-7.75,17.3) 227(-8.25,17.3) 228(-8.75,17.3) 229(-9.25,17.3) 230(-9.75,17.3) 231(-10.25,17.3) 232(-10.75,17.3) 233(-11.25,17.3) 234(-11.75,17.3) 235(-12.25,17.3) 236(-12.75,17.3) 237(-13.25,17.3) 238(-13.75,17.3) 239(-14.25,17.3) 240(-14.75,17.3)
Top Overlay:
  circle w0.25: c-16.975,15.45 r0.125
  lines w0.2: -15.825,-15.825 -15.825,15.825 15.825,15.825 15.825,-15.825 -15.825,-15.825

## PXIJ1 [mm]
pads (122):
  round 1.3 hole 0.65: A1(0,0) A2(0,2) A3(0,4) A4(0,6) A5(0,8) A6(0,10) A7(0,12) A8(0,14) A9(0,16) A10(0,18) A11(0,20) A15(0,28) A16(0,30) A17(0,32) A18(0,34) A19(0,36) A20(0,38) A21(0,40) A22(0,42) A23(0,44) A24(0,46) A25(0,48) B2(-2,2) B3(-2,4) B4(-2,6) B5(-2,8) B6(-2,10) B7(-2,12) B8(-2,14) B9(-2,16) B10(-2,18) B11(-2,20) B15(-2,28) B16(-2,30) B17(-2,32) B18(-2,34) B19(-2,36) B20(-2,38) B21(-2,40) B22(-2,42) B23(-2,44) B24(-2,46) B25(-2,48) C1(-4,0) C2(-4,2) C3(-4,4) C4(-4,6) C5(-4,8) C6(-4,10) C7(-4,12) C8(-4,14) C9(-4,16) C10(-4,18) C11(-4,20) C15(-4,28) C16(-4,30) C17(-4,32) C18(-4,34) C19(-4,36) C20(-4,38) C21(-4,40) C22(-4,42) C23(-4,44) C24(-4,46) C25(-4,48) D1(-6,0) D2(-6,2) D3(-6,4) D4(-6,6) D5(-6,8) D6(-6,10) D7(-6,12) D8(-6,14) D9(-6,16) D10(-6,18) D11(-6,20) D15(-6,28) D16(-6,30) D17(-6,32) D18(-6,34) D19(-6,36) D20(-6,38) D21(-6,40) D22(-6,42) D23(-6,44) D24(-6,46) D25(-6,48) E1(-8,0) E2(-8,2) E3(-8,4) E4(-8,6) E5(-8,8) E6(-8,10) E7(-8,12) E8(-8,14) E9(-8,16) E10(-8,18) E11(-8,20) E15(-8,28) E16(-8,30) E17(-8,32) E18(-8,34) E19(-8,36) E20(-8,38) E21(-8,40) E22(-8,42) E23(-8,44) E24(-8,46) E25(-8,48) F1(-10,0) F3(-10,4) F5(-10,8) F7(-10,12) F9(-10,16) F11(-10,20) F15(-10,28) F17(-10,32) F19(-10,36) F21(-10,40) F23(-10,44) F25(-10,48)
  round 1.3 hole 0.75: B1(-2,0)
Top Overlay:
  lines w0.254: -11,-1 -11,49 1,49 1,-1 -11,-1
